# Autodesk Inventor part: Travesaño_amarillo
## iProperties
Created: 2008-01
Part Number: Travesaño_amarillo
Document SubType Name: Modeling
Designer: eruiz-tagle
Mass: 0.434197 g
Surface Area: 9.24285 cm^2
Volume: 0.434197 cm^3
Density: 1 g/cm^3
Author: eruiz-tagle
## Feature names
1. Extrusion1
2. Hole1
3. Mirror1
4. Mirror2
5. Extrusion2
6. Mirror3
7. Fillet1
